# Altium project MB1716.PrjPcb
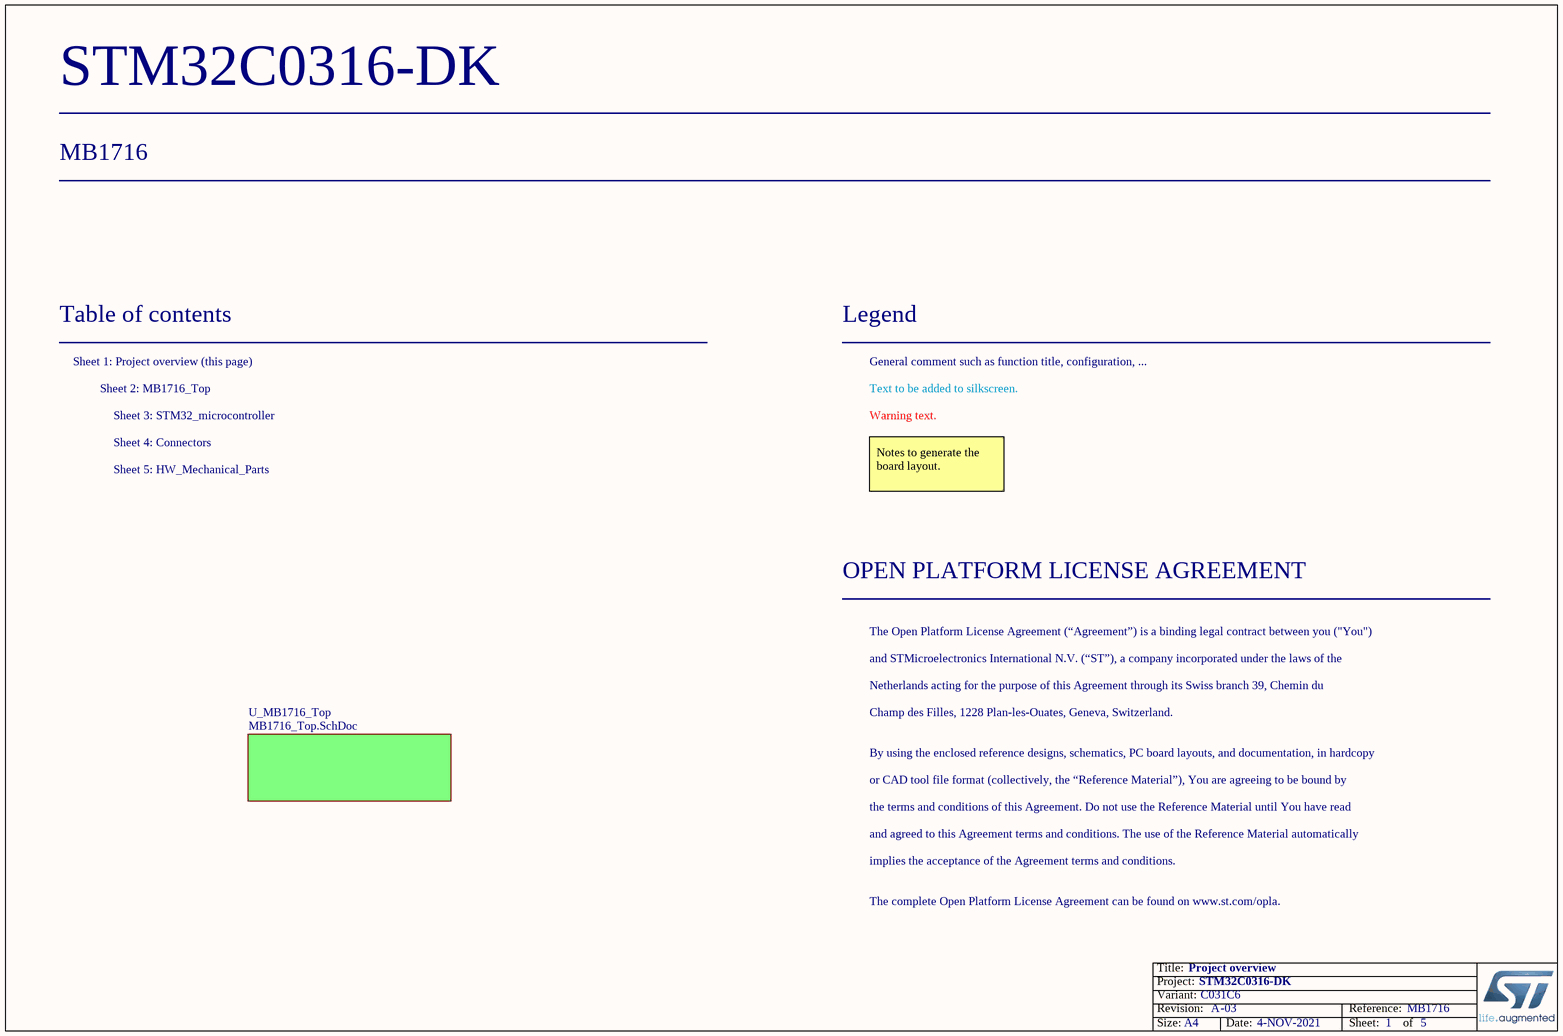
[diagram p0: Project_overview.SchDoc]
Board_Assembly_Revision: 03; Board_Document_Date: 4-NOV-2021; Board_Name: STM32C0316-DK; Board_PCB_Revision: A; Board_Reference: MB1716; VariantName: C031C6
5 sheets, 54 parts. Net scope: flat (ports and power ports of the same name join across sheets).
Board file: MB1716.PcbDoc
Sheets:
  Project_overview.SchDoc
    U_MB1716_Top = MB1716_Top.SchDoc
      U_STM32_microcontroller = STM32_microcontroller.SchDoc
      U_HW_Mechanical_Parts = HW_Mechanical_Parts.SchDoc
      U_Connectors = Connectors.SchDoc

## Sheet Project_overview.SchDoc: Project overview
size A4; Date: Not used; ApprovedBy: Not used; CheckedBy: Not used; Author: Not used; CompanyName: STMicroelectronics; DrawnBy: Not used; Engineer: Not used; Organization: Not used; Address1: Not used; Address2: Not used; Address3: Not used; Address4: Not used; DocumentNumber: Not used; Revision: Not used; SheetNumber: 1; SheetTotal: 5

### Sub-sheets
U_MB1716_Top = MB1716_Top.SchDoc: no entries

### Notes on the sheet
- Table of contents
- Sheet 1: Project overview (this page)
- Legend
- General comment such as function title, configuration, ...
- Sheet 2: MB1716_Top
- Sheet 3: STM32_microcontroller
- Sheet 4: Connectors
- Text to be added to silkscreen.
- Warning text.
- Sheet 5: HW_Mechanical_Parts
- Notes to generate the board layout.
- OPEN PLATFORM LICENSE AGREEMENT
- The Open Platform License Agreement (“Agreement”) is a binding legal contract between you ("You")
- and STMicroelectronics International N.V. (“ST”), a company incorporated under the laws of the
- Netherlands acting for the purpose of this Agreement through its Swiss branch 39, Chemin du
- Champ des Filles, 1228 Plan-les-Ouates, Geneva, Switzerland.
- By using the enclosed reference designs, schematics, PC board layouts, and documentation, in hardcopy
- or CAD tool file format (collectively, the “Reference Material”), You are agreeing to be bound by
- the terms and conditions of this Agreement. Do not use the Reference Material until You have read
- and agreed to this Agreement terms and conditions. The use of the Reference Material automatically
- implies the acceptance of the Agreement terms and conditions.
- The complete Open Platform License Agreement can be found on www.st.com/opla.

## Sheet MB1716_Top.SchDoc: Top hierarchical view
size A4; Date: Not used; ApprovedBy: Not used; CheckedBy: Not used; Author: Not used; CompanyName: STMicroelectronics; DrawnBy: Not used; Engineer: Not used; Organization: Not used; Address1: Not used; Address2: Not used; Address3: Not used; Address4: Not used; DocumentNumber: Not used; Revision: A-01-P3; SheetNumber: 2; SheetTotal: 5
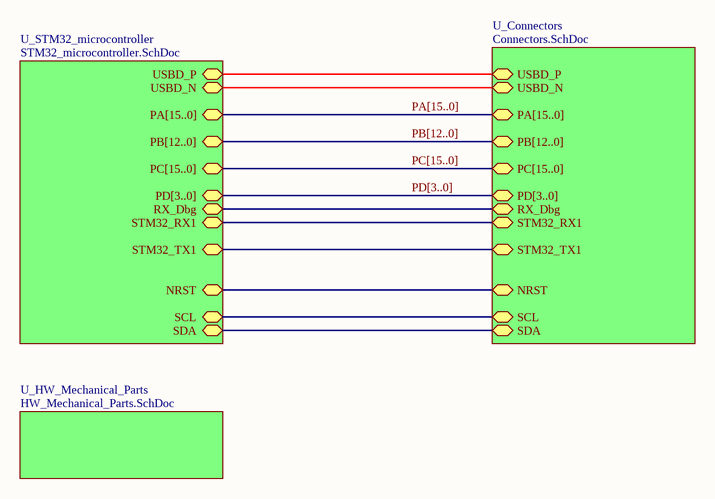
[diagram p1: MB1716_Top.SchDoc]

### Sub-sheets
U_Connectors = Connectors.SchDoc: NRST (bidir), PB[12..0] (bidir), PA[15..0] (bidir), PC[15..0] (bidir), USBD_N (bidir), USBD_P (bidir), STM32_TX1 (bidir), STM32_RX1 (bidir), PD[3..0] (bidir), SDA (bidir), SCL (bidir), RX_Dbg (bidir)
U_HW_Mechanical_Parts = HW_Mechanical_Parts.SchDoc: no entries
U_STM32_microcontroller = STM32_microcontroller.SchDoc: NRST (bidir), PB[12..0] (bidir), PA[15..0] (bidir), RX_Dbg (bidir), USBD_N (bidir), USBD_P (bidir), STM32_TX1 (bidir), STM32_RX1 (bidir), PC[15..0] (bidir), PD[3..0] (bidir), SCL (bidir), SDA (bidir)

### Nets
(unnamed): sheet U_STM32_microcontroller/NRST, sheet U_Connectors/NRST
(unnamed): sheet U_STM32_microcontroller/RX_Dbg, sheet U_Connectors/RX_Dbg  [a separate net that carries the same name]
(unnamed): sheet U_STM32_microcontroller/USBD_N, sheet U_Connectors/USBD_N  [a separate net that carries the same name]
(unnamed): sheet U_STM32_microcontroller/USBD_P, sheet U_Connectors/USBD_P  [a separate net that carries the same name]
(unnamed): sheet U_STM32_microcontroller/STM32_TX1, sheet U_Connectors/STM32_TX1  [a separate net that carries the same name]
(unnamed): sheet U_STM32_microcontroller/STM32_RX1, sheet U_Connectors/STM32_RX1  [a separate net that carries the same name]
(unnamed): sheet U_STM32_microcontroller/SCL, sheet U_Connectors/SCL  [a separate net that carries the same name]
(unnamed): sheet U_STM32_microcontroller/SDA, sheet U_Connectors/SDA  [a separate net that carries the same name]

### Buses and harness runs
bus PA[15..0] = sheet U_Connectors/PA[15..0] = sheet U_STM32_microcontroller/PA[15..0]
bus PB[12..0] = sheet U_Connectors/PB[12..0] = sheet U_STM32_microcontroller/PB[12..0]
bus PC[15..0] = sheet U_Connectors/PC[15..0] = sheet U_STM32_microcontroller/PC[15..0]
bus PD[3..0] = sheet U_Connectors/PD[3..0] = sheet U_STM32_microcontroller/PD[3..0]

## Sheet STM32_microcontroller.SchDoc: MCU
size A3; CompanyName: STMicroelectronics; Organization: Microcontrollers Division; DocumentNumber: MCD16-037; Revision: A-01; SheetNumber: 3; SheetTotal: 5; Project: STM32L476 Brisk
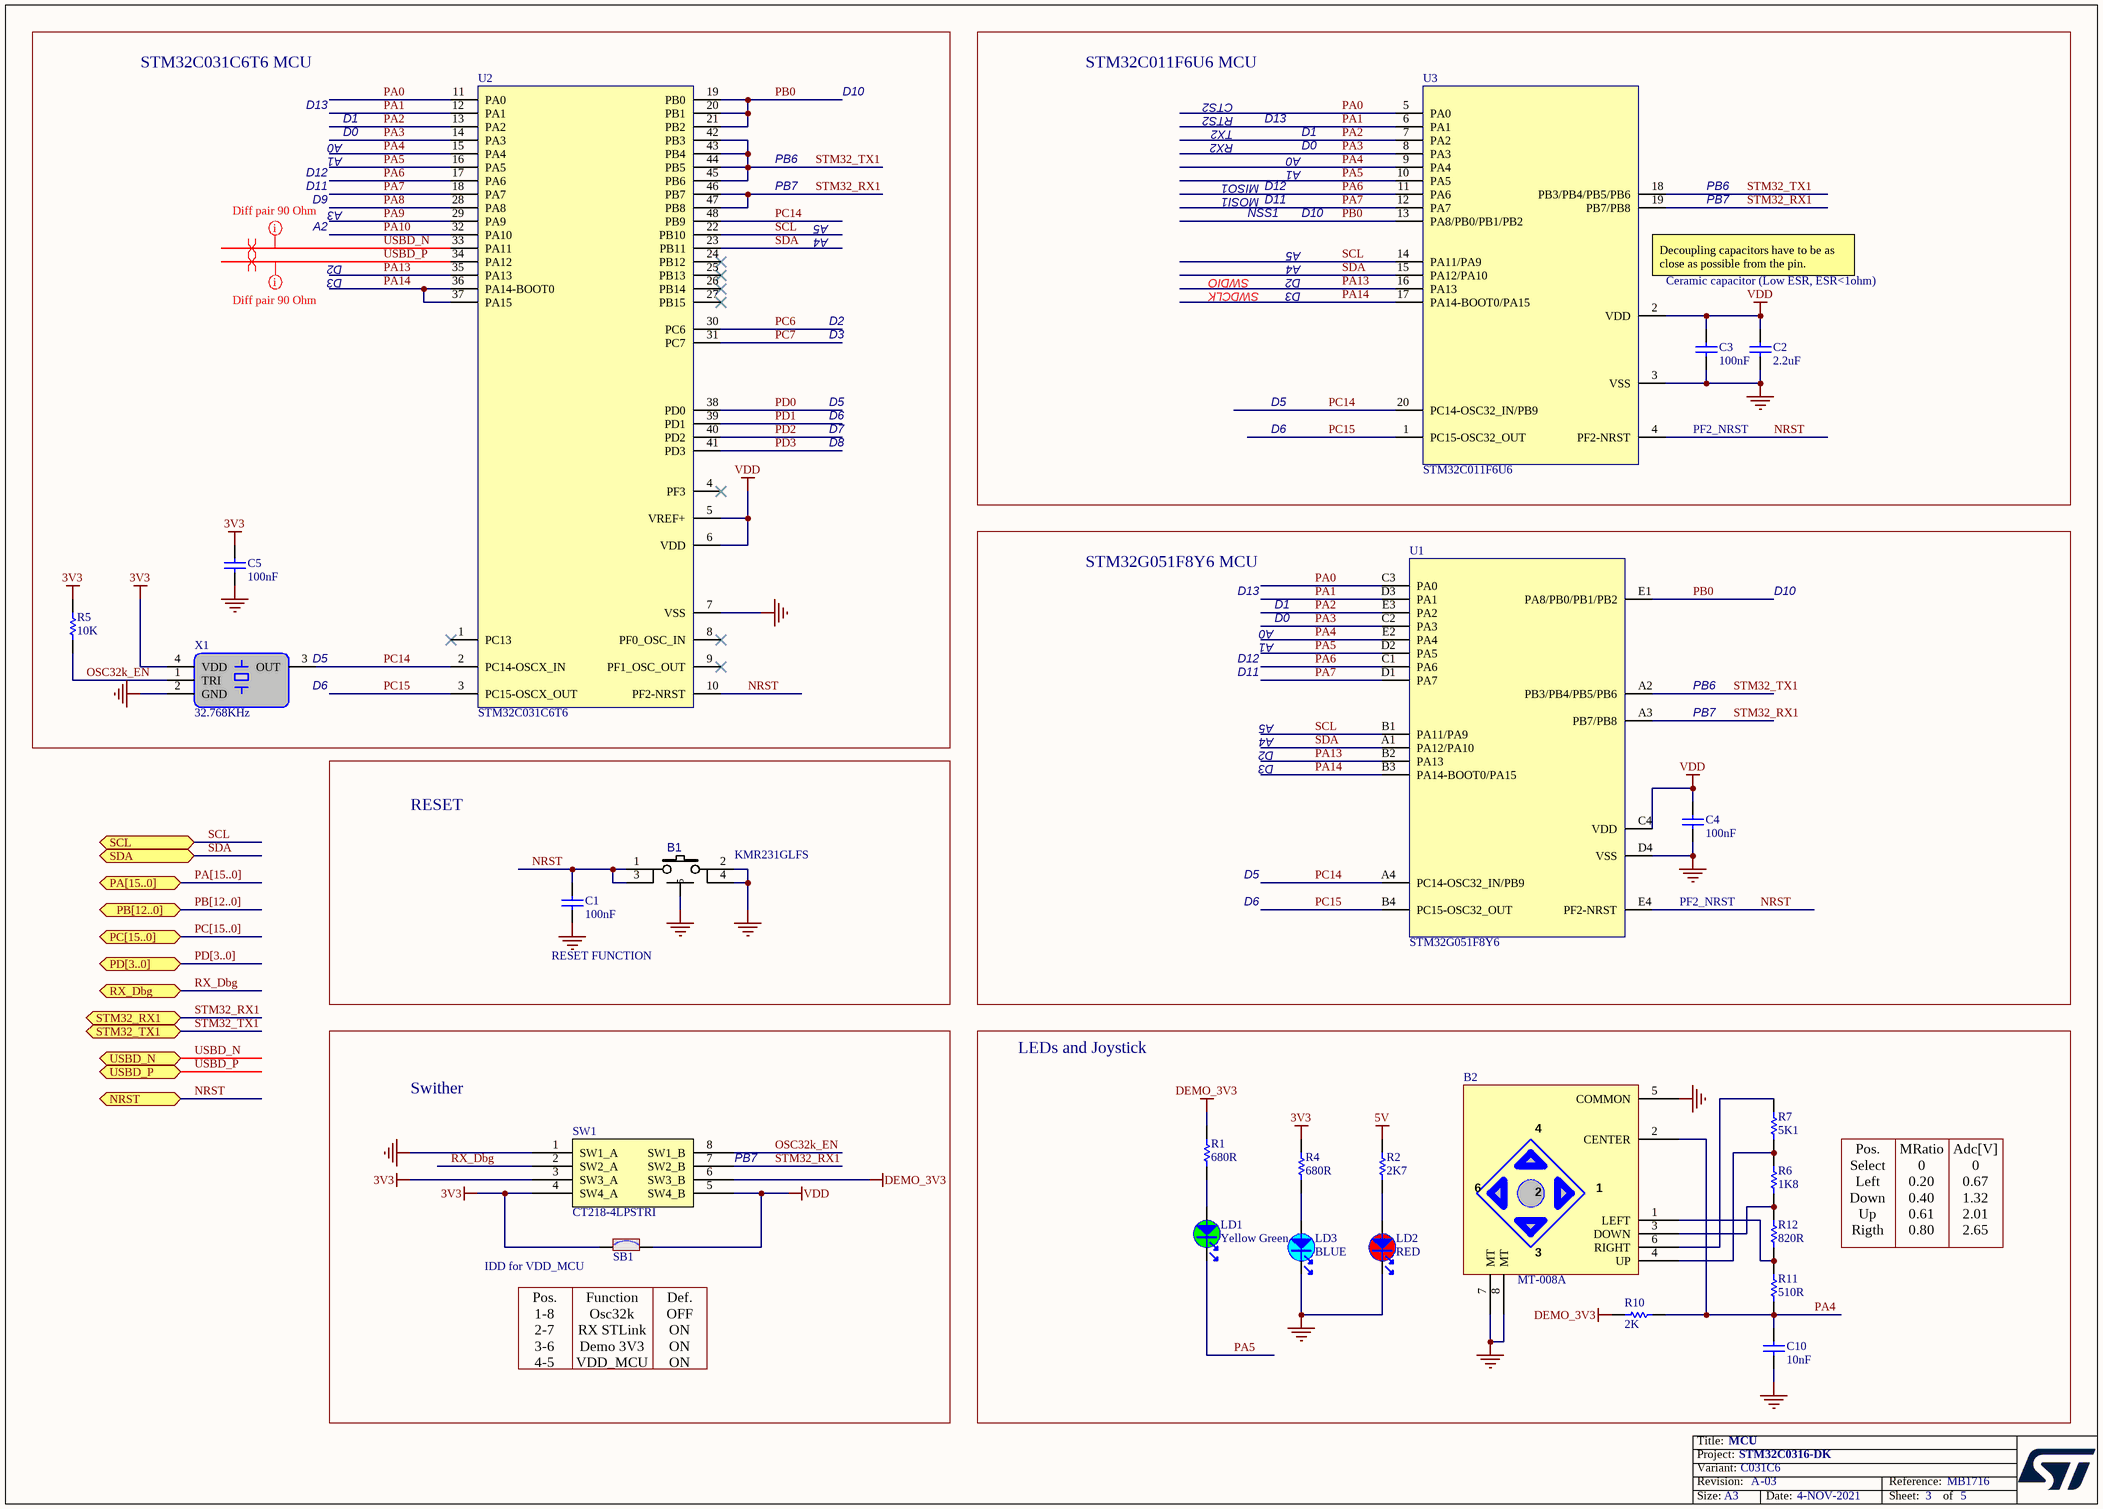
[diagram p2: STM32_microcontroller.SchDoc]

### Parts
B1  value KMR231GLFS  [SWI_C&K_Y78B23110FP__ITT_KMR231GLFS]  (hidden comment: SW-PUSH-CMS_KMR2_BLACK)
B2  value MT-008A  [SWI_XIEJIA_MT-008A_6P]  (hidden comment: Joystick MT-008A_M)
C1  value 100nF  [C0402]  (hidden comment: Capacitor)
C2  value 2.2uF  [C0603]  (hidden comment: Capacitor)
C3  value 100nF  [C0402]  (hidden comment: Capacitor)
C4  value 100nF  [C0402]  (hidden comment: Capacitor)
C5  value 100nF  [C0402]  (hidden comment: Capacitor)
C10  value 10nF  [C0402]  (hidden comment: Capacitor)
LD1  value Yellow Green  [LED_0402_EVERLIGHT_16-213SYGC/S530-E3-TR8 _YELLOW-GREEN_1A2K_H0P45]  (hidden comment: LED_green)
LD2  value RED  [LED_0402_KINGBRIGHT_KPHHS-1005SURCK_HYPER-RED_1A2K_H0P5]  (hidden comment: LED_red)
LD3  value BLUE  [LED_0402_KINGBRIGHT_KPHHS-1005QBC-D-V_BLUE_1A2K_H0P5]  (hidden comment: LED_blue)
R1  value 680R  [R0402]  (hidden comment: Resistor)
R2  value 2K7  [R0402]  (hidden comment: Resistor)
R4  value 680R  [R0402]  (hidden comment: Resistor)
R5  value 10K  [R0402]  (hidden comment: Resistor)
R6  value 1K8  [R0402]  (hidden comment: Resistor)
R7  value 5K1  [R0402]  (hidden comment: Resistor)
R10  value 2K  [R0402]  (hidden comment: Resistor)
R11  value 510R  [R0402]  (hidden comment: Resistor)
R12  value 820R  [R0402]  (hidden comment: Resistor)
SB1  SB_ON  [SOLDER-BRIDGE_R0402-0R]  (value not drawn)
SW1  value CT218-4LPSTRI  [SWI_CTS_CTS218-4LP]  (hidden comment: SWITCH_4WAY)
U1  STM32G051F8Y6  [ICC_WLCSP20_1P94X2P40_P040]
U2  STM32C031C6T6  [ICC_LQFP48_7X7_P050]
U3  STM32C011F6U6  [ICC_UFQFPN20_3X3_P050]
X1  value 32.768KHz  [CRY_ECS-327MVATX-1_2X1P6_4P]  (hidden comment: ECS-327MVATX)

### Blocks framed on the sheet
STM32C031C6T6 MCU: C5 R5 U2 X1
STM32C011F6U6 MCU: C2 C3 U3
STM32G051F8Y6 MCU: C4 U1
RESET: B1 C1
Swither: SB1 SW1
LEDs and Joystick: B2 C10 LD1-LD3 R1 R2 R4 R6 R7 R10-R12

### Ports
NRST (bidir), PA[15..0] (bidir), PB[12..0] (bidir), PC[15..0] (bidir), PD[3..0] (bidir), RX_Dbg (bidir), SCL (bidir), SDA (bidir), STM32_RX1 (bidir), STM32_TX1 (bidir), USBD_N (bidir), USBD_P (bidir)

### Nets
3V3: C5.2 R4.2 R5.2 SB1.1 SW1.3(SW3_A) SW1.4(SW4_A) X1.4(VDD)
5V: R2.2
DEMO_3V3: R1.2 R10.1 SW1.6(SW3_B)
GND: B1.2 B1.4 B1.5 B2.5(COMMON) B2.7(MT) B2.8(MT) C1.1 C2.1 C3.1 C4.1 C5.1 C10.1 LD2.2 LD3.2 SW1.1(SW1_A) U1.D4(VSS) U2.7(VSS) U3.3(VSS) X1.2(GND)
VDD: C2.2 C3.2 C4.2 SB1.2 SW1.5(SW4_B) U1.C4(VDD) U2.5(VREF+) U2.6(VDD) U3.2(VDD)
NRST: B1.1 B1.3 C1.2 U1.E4(PF2-NRST) U2.10(PF2-NRST) U3.4(PF2-NRST) ; port NRST
OSC32k_EN: R5.1 SW1.8(SW1_B) X1.1(TRI)
PA0: U1.C3(PA0) U2.11(PA0) U3.5(PA0)
PA1: U1.D3(PA1) U2.12(PA1) U3.6(PA1)
PA2: U1.E3(PA2) U2.13(PA2) U3.7(PA2)
PA3: U1.C2(PA3) U2.14(PA3) U3.8(PA3)
PA4: B2.2(CENTER) C10.2 R10.2 R11.1 U1.E2(PA4) U2.15(PA4) U3.9(PA4)
PA5: LD1.2 U1.D2(PA5) U2.16(PA5) U3.10(PA5)
PA6: U1.C1(PA6) U2.17(PA6) U3.11(PA6)
PA7: U1.D1(PA7) U2.18(PA7) U3.12(PA7)
PA8: U2.28(PA8)
PA9: U2.29(PA9)
PA10: U2.32(PA10)
PA13: U1.B2(PA13) U2.35(PA13) U3.16(PA13)
PA14: U1.B3(PA14-BOOT0/PA15) U2.36(PA14-BOOT0) U2.37(PA15) U3.17(PA14-BOOT0/PA15)
PB0: U1.E1(PA8/PB0/PB1/PB2) U2.19(PB0) U2.20(PB1) U2.21(PB2) U3.13(PA8/PB0/PB1/PB2)
PC6: U2.30(PC6)
PC7: U2.31(PC7)
PC14: U1.A4(PC14-OSC32_IN/PB9) U2.2(PC14-OSCX_IN) U2.48(PB9) U3.20(PC14-OSC32_IN/PB9) X1.3(OUT)
PC15: U1.B4(PC15-OSC32_OUT) U2.3(PC15-OSCX_OUT) U3.1(PC15-OSC32_OUT)
PD0: U2.38(PD0)
PD1: U2.39(PD1)
PD2: U2.40(PD2)
PD3: U2.41(PD3)
RX_Dbg: SW1.2(SW2_A) ; port RX_Dbg
SCL: U1.B1(PA11/PA9) U2.22(PB10) U3.14(PA11/PA9) ; port SCL
SDA: U1.A1(PA12/PA10) U2.23(PB11) U3.15(PA12/PA10) ; port SDA
STM32_RX1: SW1.7(SW2_B) U1.A3(PB7/PB8) U2.46(PB7) U2.47(PB8) U3.19(PB7/PB8) ; port STM32_RX1
STM32_TX1: U1.A2(PB3/PB4/PB5/PB6) U2.42(PB3) U2.43(PB4) U2.44(PB5) U2.45(PB6) U3.18(PB3/PB4/PB5/PB6) ; port STM32_TX1
USBD_N: U2.33(PA11) ; port USBD_N
USBD_P: U2.34(PA12) ; port USBD_P
NetB2_1: B2.1(LEFT) R11.2 R12.1
NetB2_3: B2.3(DOWN) R6.1 R12.2
NetB2_4: B2.4(UP) R6.2 R7.1
NetB2_6: B2.6(RIGHT) R7.2
NetLD1_1: LD1.1 R1.1
NetLD2_1: LD2.1 R2.1
NetLD3_1: LD3.1 R4.1

Not connected (* = marked no-connect by the designer): U2 1(PC13)* 4(PF3)* 8(PF0_OSC_IN)* 9(PF1_OSC_OUT)* 24(PB12)* 25(PB13)* 26(PB14)* 27(PB15)*

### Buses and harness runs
bus PA[15..0] = port PA[15..0]
bus PB[12..0] = port PB[12..0]
bus PC[15..0] = port PC[15..0]
bus PD[3..0] = port PD[3..0]

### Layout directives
differential pair: USBD_N, USBD_P
mark named Diff pair 90 Ohm: USBD_N, USBD_P

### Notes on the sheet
- D13
- D10
- CTS2
- RTS2
- D12
- D0
- D1
- A0
- A1
- PB6
- MISO1
- TX2
- RX2
- D11
- D9
- A2
- A3
- PB7
- A4
- A5
- MOSI1
- NSS1
- D3
- D2
- SWDIO
- SWDCLK
- (near U3) Decoupling capacitors have to be as close as possible from the pin.
- (near U3) Ceramic capacitor (Low ESR, ESR<1ohm)
- D5
- D6
- D7
- D8
- PF2_NRST
- (near X1) D6
- (near X1) D5
- RESET FUNCTION
- (near SW1) PB7
- Pos.
  Select
  Left
  Down
  Up
  Rigth
- MRatio
  0
  0.20
  0.40
  0.61
  0.80
- Adc[V]
  0
  0.67
  1.32
  2.01
  2.65
- (near SB1) IDD for VDD_MCU
- Pos.
  1-8
  2-7
  3-6
  4-5
- (near SB1) Function
  Osc32k
  RX STLink
  Demo 3V3
  VDD_MCU
- (near SB1) Def.
  OFF
  ON
  ON
  ON

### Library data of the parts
B1 = MCD-01485: Microminiature Tact Switch for SMT - KMR 2 Series - 1.9 mm height; Part_Type: Misc; Manufacturer: C&K; Part_Preference: Recommended; Provided_By: SUBCO
B2 = MCD-00132: Joystick, 4 dir, 1 OK; BMS_Part_Number: 9180124; Part_Preference: Recommended; Part_Type: Misc; Manufacturer: XIEJIA ELECTRONICS
C1 C3-C5 = MCD-00006: Capacitor, MLCC, 100nF, 16V, X7R, +/-10%, 0402, T=0.5mm; Manufacturer_Part_Number: CC0402KRX7R7BB104; Manufacturer: YAGEO; Alternate_Manufacturer_Part_Number: GCM155R71C104KA55D; Alternate_Manufacturer: MURATA; Part_Preference: Recommended; Provided_By: SUBCO; ECCN_US: EAR99; ECCN_EU: NEC; Order_Code_RS: 616-9701
C2 = MCD-00654: Capacitor, MLCC, 2.2uF, 16V, X5R, +/-10%, 0603, T=0.8mm; Manufacturer_Part_Number: CC0603KRX5R7BB225; Manufacturer: YAGEO; BMS_Part_Number: 9142001; Part_Preference: Recommended; ECCN_US: EAR99; ECCN_EU: NEC; Provided_By: SUBCO
C10 = MCD-00011: Capacitor, MLCC, 10nF, 16V, X7R, +/-10%, 0402, T=0.5mm; Manufacturer_Part_Number: CC0402KRX7R7BB103; Manufacturer: YAGEO; Part_Preference: Recommended; Provided_By: SUBCO; ECCN_US: EAR99; ECCN_EU: NEC; Order_Code_RS: 669-8688
LD1 = MCD-02330: LED, Yellow Green, 2V, 25mA, 0402, 0.45mm; Part_Type: Display; Manufacturer_Part_Number: 16-213SYGC/S530-E3/TR8; Manufacturer: EVERLIGHT; Part_Preference: Recommended; Provided_By: SUBCO
LD2 = MCD-00708: LED 0402 Red; Part_Type: Display; Manufacturer_Part_Number: KPHHS-1005SURCK; Manufacturer: KINGBRIGHT; Alternate_Manufacturer_Part_Number: LS Q976-NR-1; Alternate_Manufacturer: OSRAM OPTO SEMICONDUCTORS; Part_Preference: Recommended; Provided_By: SUBCO
LD3 = MCD-00706: LED 0402 Blue; Part_Type: Display; Manufacturer_Part_Number: KPHHS-1005QBC-D-V; Manufacturer: KINGBRIGHT; Part_Preference: Recommended; Provided_By: SUBCO; Order_Code_RS: 7730430
R1 R4 = MCD-00507: Resistor, 680R, 0402, +/-1%, 1/16W; Manufacturer_Part_Number: RC0402FR-07680RL; Manufacturer: YAGEO; Part_Preference: Recommended; ECCN_US: EAR99; ECCN_EU: NEC; Provided_By: SUBCO
R2 = MCD-00055: Resistor, 2K7, 0402, +/-1%, 1/16W; Manufacturer_Part_Number: RC0402FR-072K7L; Manufacturer: YAGEO; Part_Preference: Recommended; ECCN_US: EAR99; ECCN_EU: NEC; Provided_By: SUBCO
R5 = MCD-00053: Resistor, 10K, 0402, +/-1%, 1/16W; Manufacturer_Part_Number: RC0402FR-0710KL; Manufacturer: YAGEO; BMS_Part_Number: 9131590; Part_Preference: Recommended; ECCN_US: EAR99; ECCN_EU: NEC; Provided_By: SUBCO
R6 = MCD-00409: Resistor, 1K8, 0402, +/-1%, 1/16W; Manufacturer_Part_Number: RC0402FR-071K8L; Manufacturer: YAGEO; Part_Preference: Recommended; ECCN_US: EAR99; ECCN_EU: NEC; Provided_By: SUBCO
R7 = MCD-00333: Resistor, 5K1, 0402, +/-1%, 1/16W; Manufacturer_Part_Number: RC0402FR-075K1L; Manufacturer: YAGEO; Part_Preference: Recommended; ECCN_US: EAR99; ECCN_EU: NEC; Provided_By: SUBCO
R10 = MCD-00419: Resistor, 2K, 0402, +/-1%, 1/16W; Manufacturer_Part_Number: RC0402FR-072KL; Manufacturer: YAGEO; Part_Preference: Recommended; ECCN_US: EAR99; ECCN_EU: NEC; Provided_By: SUBCO
R11 = MCD-00064: Resistor, 510R, 0402, +/-1%, 1/16W; Manufacturer_Part_Number: RC0402FR-07510RL; Manufacturer: YAGEO; Part_Preference: Recommended; ECCN_US: EAR99; ECCN_EU: NEC; Provided_By: SUBCO
R12 = MCD-00527: Resistor, 820R, 0402, +/-1%, 1/16W; Manufacturer_Part_Number: RC0402FR-07820RL; Manufacturer: YAGEO; Part_Preference: Recommended; ECCN_US: EAR99; ECCN_EU: NEC; Provided_By: SUBCO
SB1 = MCD-01618: Solder Bridge 0402 ON; Part_Type: Misc; Manufacturer_Part_Number: RC0402JR-070RL; Manufacturer: YAGEO; Part_Preference: Recommended; Provided_By: SUBCO; Order_Code_RS: 618-5804
SW1 = MCD-00167: Quad SPST surface mount switch. 1.27mm pitch. Tinned legs.; Part_Preference: Recommended; Part_Type: Misc; Manufacturer: CTS
U1 = MCD-02303: MCU, ARM-based 32-bit MCU Cortex-M0+; Part_Type: IC; Part_Preference: Recommended; Manufacturer: STMICROELECTRONICS
U2 = MCD-02301: MCU, ARM™-based 32-bit MCU Cortex-M0+, 32KB Flash, 6KB SRAM; Part_Type: IC; Part_Preference: Recommended; Manufacturer: STMICROELECTRONICS
U3 = MCD-02313: MCU, ARM™-based 32-bit MCU Cortex-M0+, 32KB Flash, 6KB SRAM; Part_Type: IC; Part_Preference: Recommended; Manufacturer: STMICROELECTRONICS
X1 = MCD-02672: Oscillator, SPXO, 32.768KHz, +/-25ppm, square wave, 1.6V~3.6V, 2x1.6mm; Part_Type: Crystal_Osc; Part_Preference: Recommended; Manufacturer: NDK; Manufacturer_Part_Number: NZ2016SHB-32.768kHz-END6031A

## Sheet HW_Mechanical_Parts.SchDoc: HW Mechanical parts
size A4; SheetNumber: 5; SheetTotal: 5
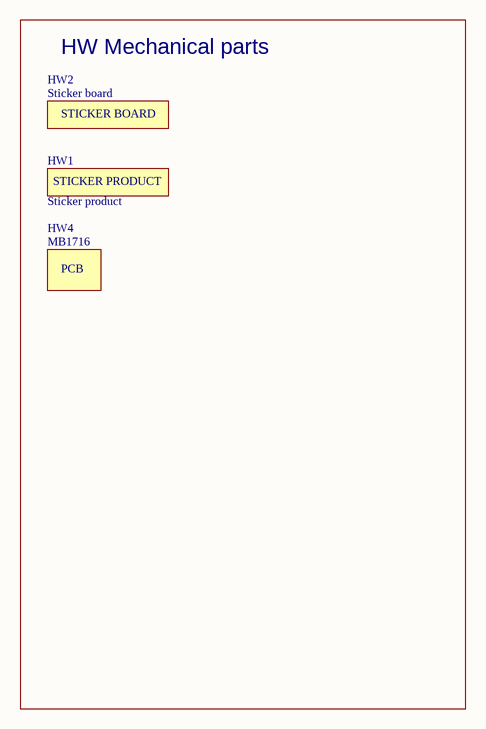
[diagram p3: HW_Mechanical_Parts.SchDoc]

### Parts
HW1  value Sticker product  [STICKER_PRODUCT_15X5]  (hidden comment: STICKER_PRODUCT)  (no BOM)
HW2  value Sticker board  [STICKER_Board_15X5]  (hidden comment: STICKER_BOARD)  (no BOM)
HW4  value MB1716  (hidden comment: PCB)  (mechanical)

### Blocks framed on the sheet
HW Mechanical parts: HW1 HW2 HW4

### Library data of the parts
HW1 = MCD-02191: Sticker product 15x5 mm; Part_Type: Misc; Part_Preference: Recommended
HW2 = MCD-02192: Sticker board 15x5 mm; Part_Type: Misc; Part_Preference: Recommended
HW4 = MCD-02487: MB1716 PCB; Part_Preference: Recommended; Provided_By: SUBCO

## Sheet Connectors.SchDoc: Connectors
size A4; Date: Not used; ApprovedBy: Not used; CheckedBy: Not used; Author: Not used; CompanyName: STMicroelectronics; DrawnBy: Not used; Engineer: Not used; Organization: Not used; Address1: Not used; Address2: Not used; Address3: Not used; Address4: Not used; DocumentNumber: Not used; Revision: Not used; SheetNumber: 4; SheetTotal: 5
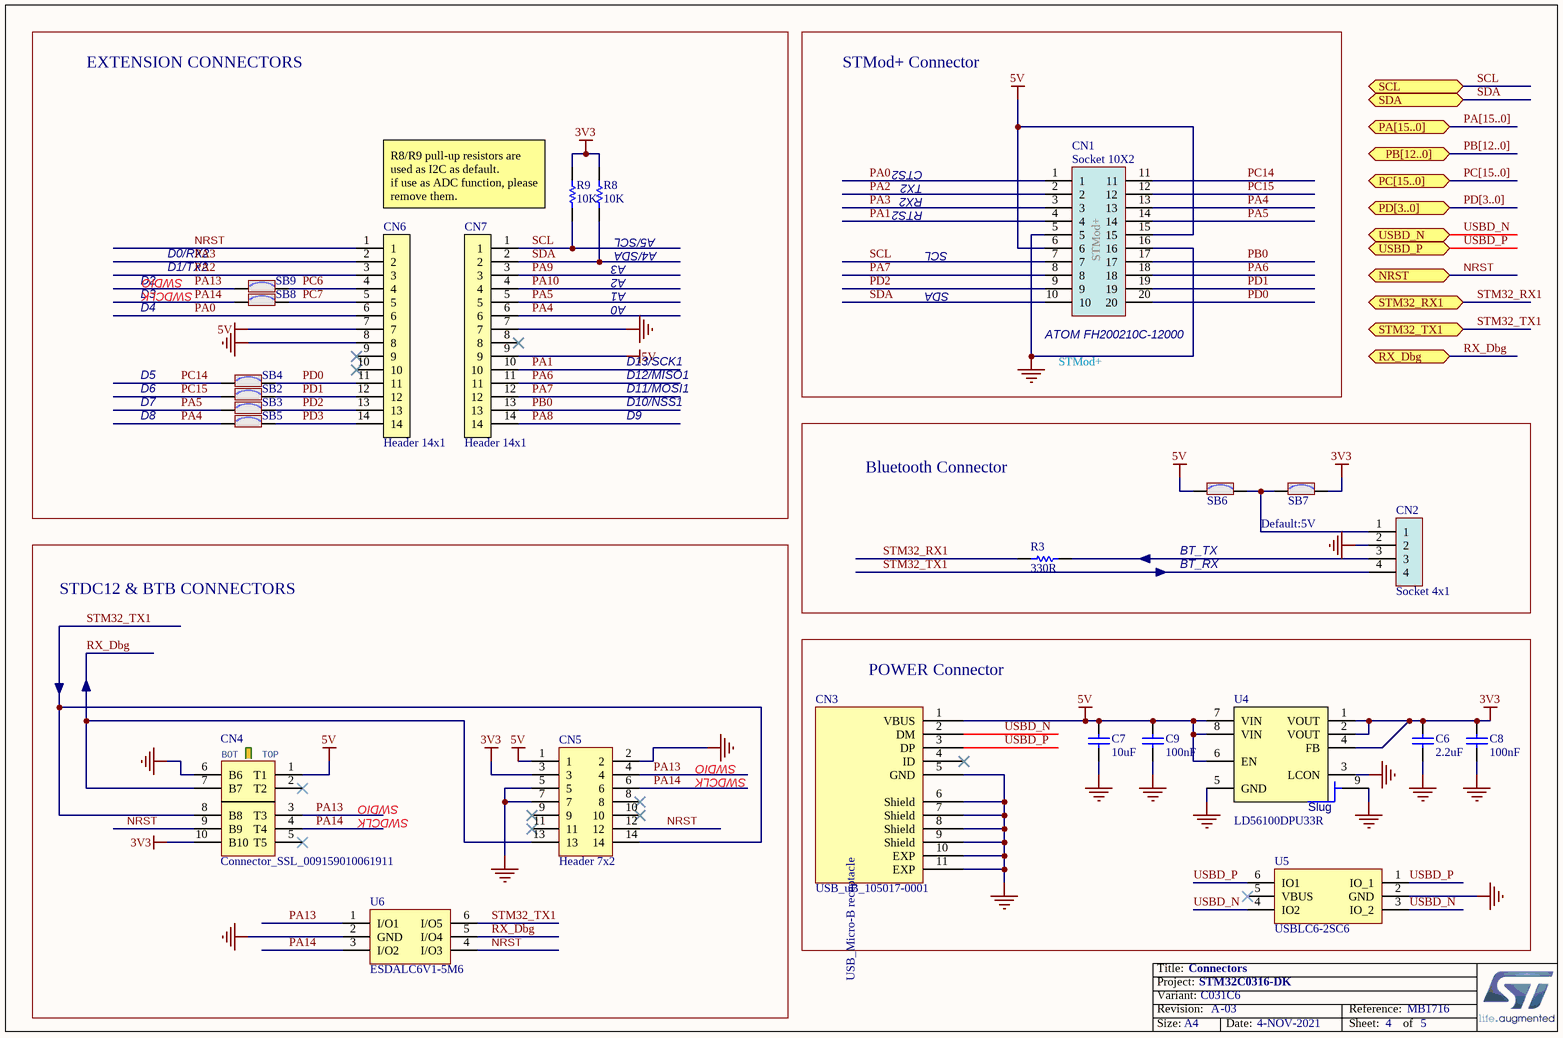
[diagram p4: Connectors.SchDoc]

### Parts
C6  value 2.2uF  [C0603]  (hidden comment: Capacitor)
C7  value 10uF  [C0603]  (hidden comment: Capacitor)
C8  value 100nF  [C0402]  (hidden comment: Capacitor)
C9  value 100nF  [C0402]  (hidden comment: Capacitor)
CN1  value Socket 10X2  [CON_SAMTEC_SQT-110-01-F-D-RA__STMOD+]  (hidden comment: Socket 10X2 STMod+)
CN2  Socket 4x1  [CON_SAMTEC_SSW-104-02-G-S-RA]
CN3  value USB_uB_105017-0001  [CON_USBMICROB_MOLEX_105017-0001_H2P90]  (hidden comment: USB_uB_105017.0001)
CN4  value Connector_SSL_009159010061911  [CON_AVX_009159010061911_BTB]  (hidden comment: BTB010_061R)
CN5  Header 7x2  [CON_STDC14_Receiver_MEDIUM_WITH_STDC14_3D]
CN6  Header 14x1  [CON_SAMTEC_TSW-114-07-X-S]
CN7  Header 14x1  [CON_SAMTEC_TSW-114-07-X-S]
R3  value 330R  [R0402]  (hidden comment: Resistor)
R8  value 10K  [R0402]  (hidden comment: Resistor)
R9  value 10K  [R0402]  (hidden comment: Resistor)
SB2  SB_ON  [SOLDER-BRIDGE_R0402-0R]  (value not drawn)
SB3  SB_ON  [SOLDER-BRIDGE_R0402-0R]  (value not drawn)
SB4  SB_ON  [SOLDER-BRIDGE_R0402-0R]  (value not drawn)
SB5  SB_ON  [SOLDER-BRIDGE_R0402-0R]  (value not drawn)
SB6  SB_ON  [SOLDER-BRIDGE_R0402-0R]  (value not drawn)
SB7  SB_ON  [SOLDER-BRIDGE_R0402-0R]  (value not drawn)
SB8  SB_ON  [SOLDER-BRIDGE_R0402-0R]  (value not drawn)
SB9  SB_ON  [SOLDER-BRIDGE_R0402-0R]  (value not drawn)
U4  value LD56100DPU33R  [ESD_DFN8-EPAD_1P6X1P2_P040_H0P45]  (hidden comment: LD56100)
U5  USBLC6-2SC6  [ESD_SOT23-6L]
U6  ESDALC6V1-5M6  [ESD_UQFN-6L_1P45X1_P050]

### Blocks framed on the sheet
EXTENSION CONNECTORS: CN6 CN7 R8 R9 SB2-SB5 SB8 SB9
STMod+ Connector: CN1
Bluetooth Connector: CN2 R3 SB6 SB7
STDC12 & BTB CONNECTORS: CN4 CN5 U6
POWER Connector: C6-C9 CN3 U4 U5

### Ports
NRST (bidir), PA[15..0] (bidir), PB[12..0] (bidir), PC[15..0] (bidir), PD[3..0] (bidir), RX_Dbg (bidir), SCL (bidir), SDA (bidir), STM32_RX1 (bidir), STM32_TX1 (bidir), USBD_N (bidir), USBD_P (bidir)

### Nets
3V3: C6.2 C8.2 CN4.10(B10) CN5.3 R8.2 R9.2 SB7.2 U4.1(VOUT) U4.2(VOUT) U4.4(FB)
5V: C7.2 C9.2 CN1.6 CN1.15 CN3.1(VBUS) CN4.1(T1) CN5.1 CN6.7 CN7.9 SB6.1 U4.6(EN) U4.7(VIN) U4.8(VIN)
GND: C6.1 C7.1 C8.1 C9.1 CN1.5 CN1.16 CN2.2 CN3.5(GND) CN3.6(Shield) CN3.7(Shield) CN3.8(Shield) CN3.9(Shield) CN3.10(EXP) CN3.11(EXP) CN4.6(B6) CN5.2 CN5.5 CN5.7 CN6.8 CN7.7 U4.3(LCON) U4.5(GND) U4.9(GND) U5.2(GND) U6.2(GND)
NRST: CN4.9(B9) CN5.12 CN6.1 U6.4(I/O3) ; port NRST
PA0: CN1.1 CN6.6
PA1: CN1.4 CN7.10
PA2: CN1.2 CN6.3
PA3: CN1.3 CN6.2
PA4: CN1.13 CN7.6 SB5.1
PA5: CN1.14 CN7.5 SB3.1
PA6: CN1.18 CN7.11
PA7: CN1.8 CN7.12
PA8: CN7.14
PA9: CN7.3
PA10: CN7.4
PA13: CN4.3(T3) CN5.4 SB9.1 U6.1(I/O1)
PA14: CN4.4(T4) CN5.6 SB8.1 U6.3(I/O2)
PB0: CN1.17 CN7.13
PC6: CN6.4 SB9.2
PC7: CN6.5 SB8.2
PC14: CN1.11 SB4.1
PC15: CN1.12 SB2.1
PD0: CN1.20 CN6.11 SB4.2
PD1: CN1.19 CN6.12 SB2.2
PD2: CN1.9 CN6.13 SB3.2
PD3: CN6.14 SB5.2
RX_Dbg: CN4.7(B7) CN5.13 U6.5(I/O4) ; port RX_Dbg
SCL: CN1.7 CN7.1 R9.1 ; port SCL
SDA: CN1.10 CN7.2 R8.1 ; port SDA
STM32_RX1: R3.1 ; port STM32_RX1
STM32_TX1: CN2.4 CN4.8(B8) CN5.14 U6.6(I/O5) ; port STM32_TX1
USBD_N: CN3.2(DM) U5.3(IO_2) U5.4(IO2) ; port USBD_N
USBD_P: CN3.3(DP) U5.1(IO_1) U5.6(IO1) ; port USBD_P
NetCN2_1: CN2.1 SB6.2 SB7.1
NetCN2_3: CN2.3 R3.2

Not connected (* = marked no-connect by the designer): CN3 4(ID)*; CN4 2(T2)* 5(T5)*; CN5 8* 9* 10* 11*; CN6 9* 10*; CN7 8*; U5 5(VBUS)*

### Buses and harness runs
bus PA[15..0] = port PA[15..0]
bus PB[12..0] = port PB[12..0]
bus PC[15..0] = port PC[15..0]
bus PD[3..0] = port PD[3..0]

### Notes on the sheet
- CTS2
- TX2
- R8/R9 pull-up resistors are used as I2C as default.
  if use as ADC function, please remove them.
- A4/SDA
- A5/SCL
- RX2
- RTS2
- SCL
- D2
- D4
- D3
- SWDIO
- SWDCLK
- D0/RX2
- D1/TX2
- A0
- A1
- A2
- A3
- SDA
- D5
- D13/SCK1
- D12/MISO1
- (near CN1) ATOM FH200210C-12000
- STMod+
- D6
- D7
- D8
- D9
- D10/NSS1
- D11/MOSI1
- BT_RX
- BT_TX
- Default:5V

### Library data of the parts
C6 = MCD-00654: as C2 on sheet STM32_microcontroller
C7 = MCD-01124: Capacitor, MLCC, 10uF, 10V, X5R, +/-10%, 0603, T=0.8mm; Manufacturer_Part_Number: GRM188R61A106KAAL; Manufacturer: MURATA; Part_Preference: Recommended; ECCN_US: EAR99; ECCN_EU: NEC; Provided_By: SUBCO; Order_Code_RS: 170-6258
C8 C9 = MCD-00006: as C1 on sheet STM32_microcontroller
CN1 = MCD-00309: Socket, 10x2, 2mm, RA, TH, T=6.35mm/2.29mm; Part_Type: Connector; Manufacturer_Part_Number: SQT-110-01-F-D-RA; Manufacturer: SAMTEC; Alternate_Manufacturer_Part_Number: FH200020C-12300;CNT-F200-2*10-GD-635/2.3; Alternate_Manufacturer: JIUBABA;CONNECT; Part_Preference: Recommended; Order_Code_RS: 180-1541
CN2 = MCD-02305: Socket, 4x1, 2.54mm, RA, TH, T=10.67/2.41mm; Part_Type: Connector; Part_Preference: Recommended; Manufacturer: SAMTEC; Manufacturer_Part_Number: SSW-104-02-G-S-RA; Order_Code_RS: 765-5641
CN3 = MCD-00028: MicroUSB_TypeB, 5pins, 0.65mm, RA, SMD, T=2.9mm; Part_Type: Connector; Manufacturer_Part_Number: 1050170001; Manufacturer: MOLEX; Part_Preference: Recommended; Provided_By: SUBCO; Order_Code_RS: 848-6764
CN4 = MCD-02332: Connector_SSL, 10 Position Adapter, Bridge Board to Board - Card Edge 0.079" (2.00mm); Part_Preference: Recommended; Manufacturer: AVX; Manufacturer_Part_Number: 009159010061911; Order_Code_RS: 174-4973
CN5 = MCD-01241: Header, 7x2, 1.27mm, VR, SMD, T=5.97mm; Part_Preference: Recommended; Part_Type: Connector; Manufacturer: SAMTEC; Manufacturer_Part_Number: FTSH-107-01-L-DV-K; Order_Code_RS: 179-9021
CN6 CN7 = MCD-02306: Header, 14x1, 2,54mm, VR, TH, T=5.84mm/2.54mm; Part_Type: Connector; Part_Preference: Recommended; Manufacturer: SAMTEC; Manufacturer_Part_Number: TSW-114-07-G-S; Order_Code_RS: 180-2010
R3 = MCD-00062: Resistor, 330R, 0402, +/-1%, 1/16W; Manufacturer_Part_Number: RC0402FR-07330RL; Manufacturer: YAGEO; Part_Preference: Recommended; ECCN_US: EAR99; ECCN_EU: NEC; Provided_By: SUBCO
R8 R9 = MCD-00053: as R5 on sheet STM32_microcontroller
SB2-SB9 = MCD-01618: as SB1 on sheet STM32_microcontroller
U4 = MCD-02304: LDO, 1 A very low dropout fast transient ultra-low noise linear regulator; Part_Type: IC; Part_Preference: Recommended; Manufacturer: STMICROELECTRONICS; Order_Code_RS: 192-4846
U5 = MCD-00163: Very low capacitance ESD protection; Part_Type: IC; Manufacturer: STMICROELECTRONICS; BMS_Part_Number: 9151075; Part_Preference: Recommended; Manufacturer_HQ_COO: EU
U6 = MCD-01457: ESD protection , 5 lines; BMS_Part_Number: 9151139; Part_Type: Diode; Part_Preference: Recommended; Manufacturer: STMICROELECTRONICS; Manufacturer_HQ_COO: EU

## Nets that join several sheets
3V3: STM32_microcontroller (7 pins), Connectors (10 pins)
5V: STM32_microcontroller (R2.2), Connectors (13 pins)
GND: STM32_microcontroller (19 pins), Connectors (25 pins)
NRST: STM32_microcontroller (6 pins), Connectors (CN4.9 CN5.12 CN6.1 U6.4)
PA0: STM32_microcontroller (U1.C3 U2.11 U3.5), Connectors (CN1.1 CN6.6)
PA1: STM32_microcontroller (U1.D3 U2.12 U3.6), Connectors (CN1.4 CN7.10)
PA2: STM32_microcontroller (U1.E3 U2.13 U3.7), Connectors (CN1.2 CN6.3)
PA3: STM32_microcontroller (U1.C2 U2.14 U3.8), Connectors (CN1.3 CN6.2)
PA4: STM32_microcontroller (7 pins), Connectors (CN1.13 CN7.6 SB5.1)
PA5: STM32_microcontroller (LD1.2 U1.D2 U2.16 U3.10), Connectors (CN1.14 CN7.5 SB3.1)
PA6: STM32_microcontroller (U1.C1 U2.17 U3.11), Connectors (CN1.18 CN7.11)
PA7: STM32_microcontroller (U1.D1 U2.18 U3.12), Connectors (CN1.8 CN7.12)
PA8: STM32_microcontroller (U2.28), Connectors (CN7.14)
PA9: STM32_microcontroller (U2.29), Connectors (CN7.3)
PA10: STM32_microcontroller (U2.32), Connectors (CN7.4)
PA13: STM32_microcontroller (U1.B2 U2.35 U3.16), Connectors (CN4.3 CN5.4 SB9.1 U6.1)
PA14: STM32_microcontroller (U1.B3 U2.36 U2.37 U3.17), Connectors (CN4.4 CN5.6 SB8.1 U6.3)
PB0: STM32_microcontroller (5 pins), Connectors (CN1.17 CN7.13)
PC6: STM32_microcontroller (U2.30), Connectors (CN6.4 SB9.2)
PC7: STM32_microcontroller (U2.31), Connectors (CN6.5 SB8.2)
PC14: STM32_microcontroller (5 pins), Connectors (CN1.11 SB4.1)
PC15: STM32_microcontroller (U1.B4 U2.3 U3.1), Connectors (CN1.12 SB2.1)
PD0: STM32_microcontroller (U2.38), Connectors (CN1.20 CN6.11 SB4.2)
PD1: STM32_microcontroller (U2.39), Connectors (CN1.19 CN6.12 SB2.2)
PD2: STM32_microcontroller (U2.40), Connectors (CN1.9 CN6.13 SB3.2)
PD3: STM32_microcontroller (U2.41), Connectors (CN6.14 SB5.2)
RX_Dbg: STM32_microcontroller (SW1.2), Connectors (CN4.7 CN5.13 U6.5)
SCL: STM32_microcontroller (U1.B1 U2.22 U3.14), Connectors (CN1.7 CN7.1 R9.1)
SDA: STM32_microcontroller (U1.A1 U2.23 U3.15), Connectors (CN1.10 CN7.2 R8.1)
STM32_RX1: STM32_microcontroller (5 pins), Connectors (R3.1)
STM32_TX1: STM32_microcontroller (6 pins), Connectors (CN2.4 CN4.8 CN5.14 U6.6)
USBD_N: STM32_microcontroller (U2.33), Connectors (CN3.2 U5.3 U5.4)
USBD_P: STM32_microcontroller (U2.34), Connectors (CN3.3 U5.1 U5.6)

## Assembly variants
C031C6: not fitted CN4 CN6 CN7 CN7 CN7 D1 D2 D4 D6 D8 D12 D13 D14 D15 D16 D17 D18 D19 D20 D21 SB1 SB2 SB2 SB3 SB3 SB4 SB4 SB5 SB5 SB6 SB7 SB8 SB8 SB9 SB9 U2 U2 U2 U4 U4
